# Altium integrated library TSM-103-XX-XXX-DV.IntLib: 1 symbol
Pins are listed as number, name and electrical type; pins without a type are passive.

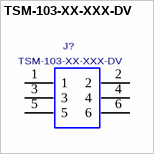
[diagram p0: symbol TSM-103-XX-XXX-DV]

## TSM-103-XX-XXX-DV
designator J?
DOUBLE ROW SURFACE MOUNT TERMINAL STRIP; MANUFACTURER: SAMTEC
footprint TSM-103-XX-XXX-DV
footprint TSM-103-XX-XXX-DV
pins: 1, 2, 3, 4, 5, 6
